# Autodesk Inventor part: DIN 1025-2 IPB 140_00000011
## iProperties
Created: 2006-02
Part Number: DIN 1025-2 IPB 140_00000011
Material: Default
Document SubType Name: Modeling
Designer: 40664
Manufacturer: Standard
Standards Organization: Custom
Stock Number: DIN 1025-2 IPB 140
Mass: 11082.7 g
Surface Area: 20865.2 cm^2
Volume: 11082.7 cm^3
Density: 1 g/cm^3
G_L: 2580.000 mm
G_W: 140.000 mm
G_H: 140.000 mm
AFG_Item: IPB 140
CSToolsMass: 11.0
CSToolsVolume: 11082691.0
CSToolsArea: 20865.0
Author: 40664
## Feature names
1. AFG_Detailed_DIN 1025-2 IPB 140_00000011 [Extrusion]
2. AFG_Simplified_DIN 1025-2 IPB 140_00000011 [Extrusion]
